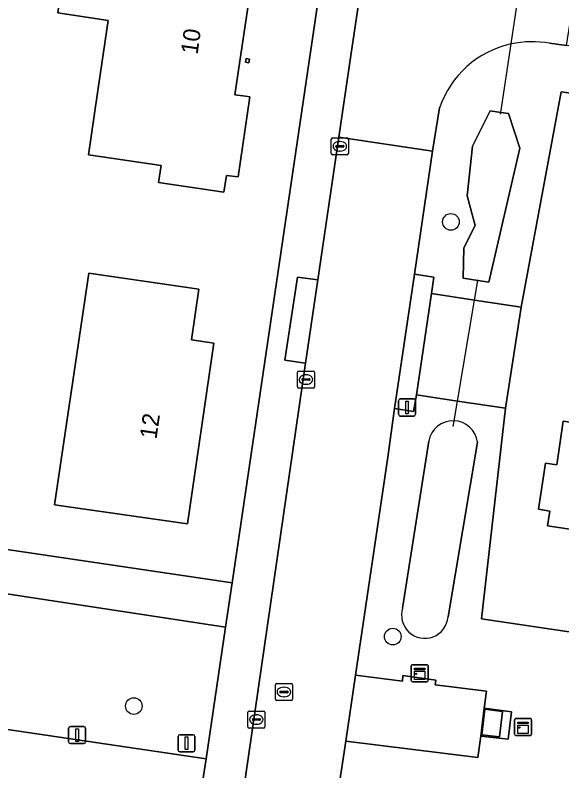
# Model space of a CAD drawing. Extents: x 164148 to 165261, y 382513 to 383432.
# Drawn here: x 164640.66 to 164672.77, y 383009.51 to 383053.88 of the extents above; entities that cross this region are included whole.
import ezdxf

# ---------------------------------------------------------------- set-up
doc = ezdxf.new("R2010")
doc.units = 0
for name, color, linetype in [('IMGEO_Boom', 7, 'Continuous'), ('IMGEO_Duiker', 7, 'Continuous'), ('IMGEO_Erf', 7, 'Continuous'), ('IMGEO_Fietspad_gesloten', 7, 'Continuous'), ('IMGEO_Greppel_droge_sloot', 7, 'Continuous'), ('IMGEO_Groenvoorziening', 7, 'Continuous'), ('IMGEO_Hek', 7, 'Continuous'), ('IMGEO_Kast', 7, 'Continuous'), ('IMGEO_Kolk', 7, 'Continuous'), ('IMGEO_Lichtmast', 7, 'Continuous'), ('IMGEO_Pand', 7, 'Continuous'), ('IMGEO_Pand_nummerreeks', 7, 'Continuous'), ('IMGEO_Rijbaan_lokaal_open', 7, 'Continuous'), ('IMGEO_Rioolput', 7, 'Continuous'), ('IMGEO_Verkeersbordpaal', 7, 'Continuous'), ('IMGEO_Voetpad_gesloten', 7, 'Continuous'), ('IMGEO_Voetpad_open', 7, 'Continuous')]:
    doc.layers.add(name, color=color, linetype=linetype)

msp = doc.modelspace()

# ---------------------------------------------------------------- linework, layer by layer
at = {"layer": 'IMGEO_Boom'}
for centre in [(164666.253, 383041.744), (164662.839, 383017.391), (164647.634, 383013.315)]:
    msp.add_circle(centre, 0.489, dxfattribs=at)
at = {"layer": 'IMGEO_Duiker'}
for points in [[(164669.17, 383048.067), (164669.186, 383048.171), (164669.783, 383052.194), (164670.585, 383057.59), (164670.896, 383059.687), (164671.713, 383065.185), (164671.811, 383065.842)], [(164666.384, 383029.725), (164666.441, 383030.064), (164666.638, 383031.227), (164667.64, 383037.152), (164667.835, 383038.307), (164667.844, 383038.358)]]:
    msp.add_lwpolyline(points, dxfattribs=at)
at = {"layer": 'IMGEO_Erf'}
msp.add_lwpolyline([(164623.816, 383163.728), (164623.27, 383160.3), (164619.179, 383132.443), (164618.352, 383126.809), (164615.891, 383110.249), (164614.945, 383103.98), (164613.433, 383093.793), (164612.816, 383089.325), (164610.85, 383076.068), (164610.275, 383072.012), (164608.947, 383063.175), (164608.549, 383060.35), (164603.815, 383028.066), (164603.697, 383027.909), (164653.403, 383020.558), (164672.613, 383150.649)], dxfattribs=at)
for points in [[(164643.979, 383059.556), (164649.903, 383058.694), (164649.464, 383055.724), (164653.421, 383055.143), (164654.417, 383054.988), (164653.922, 383051.582), (164653.571, 383049.213), (164654.187, 383049.123), (164654.45, 383049.082), (164653.769, 383044.382), (164653.075, 383044.477), (164652.926, 383043.491), (164649.091, 383044.05), (164649.237, 383045.049), (164644.968, 383045.674), (164645.482, 383049.186), (164646.131, 383053.57), (164643.171, 383054.013)], [(164654.422, 383051.297), (164654.384, 383051.092), (164654.191, 383051.127), (164654.228, 383051.332)], [(164773.625, 383034.37), (164756.914, 383036.848), (164756.945, 383037.007), (164750.961, 383037.884), (164745.467, 383038.7), (164743.325, 383039.011), (164732.535, 383040.594), (164726.832, 383041.442), (164721.322, 383042.249), (164719.176, 383042.567), (164708.591, 383044.131), (164702.568, 383045.027), (164697.666, 383045.734), (164696.644, 383045.892), (164694.5, 383046.223), (164676.627, 383048.817), (164672.72, 383049.384), (164670.369, 383036.742), (164669.457, 383030.808), (164668.043, 383018.43), (164792.926, 382999.883), (164794.329, 383009.577), (164793.988, 383009.985)], [(164644.985, 383038.74), (164651.453, 383037.79), (164651.024, 383034.828), (164652.338, 383034.618), (164650.781, 383024.013), (164642.976, 383025.139)], [(164690.562, 383027.137), (164683.784, 383028.147), (164682.464, 383019.289), (164675.536, 383020.322), (164675.979, 383023.295), (164671.929, 383023.898), (164672.059, 383024.768), (164671.396, 383024.867), (164671.8, 383027.577), (164672.463, 383027.479), (164672.845, 383030.044), (164676.882, 383029.443), (164677.368, 383032.706), (164691.087, 383030.663)]]:
    msp.add_lwpolyline(points, close=True, dxfattribs=at)
at = {"layer": 'IMGEO_Fietspad_gesloten'}
msp.add_lwpolyline([(164606.207, 383013.843), (164611.224, 383013.148), (164651.419, 383007.225), (164651.876, 383010.215), (164622.034, 383014.618), (164609.803, 383016.423), (164601.968, 383017.579)], dxfattribs=at)
at = {"layer": 'IMGEO_Greppel_droge_sloot'}
msp.add_lwpolyline([(164669.625, 383048.111), (164669.186, 383048.171), (164668.547, 383048.259), (164667.511, 383046.182), (164667.197, 383043.278), (164667.674, 383041.533), (164667.01, 383040.213), (164666.963, 383038.448), (164667.835, 383038.307), (164668.469, 383038.205), (164670.288, 383046.068)], close=True, dxfattribs=at)
for points in [[(164664.949, 383028.878), (164663.413, 383019.071)], [(164666.087, 383018.551), (164667.82, 383028.802)]]:
    msp.add_lwpolyline(points, dxfattribs=at)
for centre, radius, start, end in [((164666.378, 383028.611), 1.454, 7.5389, 169.4284), ((164664.721, 383018.663), 1.37, 162.681, 355.3096)]:
    msp.add_arc(centre, radius, start, end, dxfattribs=at)
at = {"layer": 'IMGEO_Groenvoorziening'}
for points in [[(164676.401, 383051.606), (164673.036, 383052.095), (164672.044, 383052.229)], [(164672.72, 383049.384), (164676.627, 383048.817), (164676.862, 383050.358), (164676.912, 383050.687)], [(164665.587, 383048.434), (164665.176, 383045.892), (164664.112, 383038.673), (164665.241, 383038.503), (164665.117, 383037.531), (164667.64, 383037.152), (164670.369, 383036.742), (164672.72, 383049.384)], [(164792.926, 382999.883), (164668.043, 383018.43), (164669.457, 383030.808), (164666.638, 383031.227), (164664.234, 383031.584), (164664.063, 383030.618), (164662.945, 383030.79), (164662.544, 383027.92), (164660.646, 383015.127), (164663.404, 383014.779), (164663.437, 383015.117), (164665.365, 383014.843), (164665.318, 383014.554), (164668.337, 383014.189), (164668.204, 383013.184), (164669.801, 383012.974), (164669.613, 383011.378), (164668.005, 383011.557), (164667.823, 383010.303), (164660.073, 383011.264), (164659.708, 383008.804), (164765.127, 382992.769)], [(164663.413, 383019.071), (164664.949, 383028.878)], [(164667.82, 383028.802), (164666.087, 383018.551)]]:
    msp.add_lwpolyline(points, dxfattribs=at)
for points in [[(164670.288, 383046.068), (164668.469, 383038.205), (164667.835, 383038.307), (164666.963, 383038.448), (164667.01, 383040.213), (164667.674, 383041.533), (164667.197, 383043.278), (164667.511, 383046.182), (164668.547, 383048.259), (164669.186, 383048.171), (164669.625, 383048.111)], [(164603.697, 383027.909), (164603.299, 383025.53), (164616.839, 383023.466), (164616.85, 383023.465), (164619.033, 383023.132), (164620.11, 383022.968), (164653.018, 383017.951), (164653.403, 383020.558)], [(164619.033, 383023.132), (164620.384, 383022.746), (164621.194, 383022.137), (164622.173, 383020.201), (164622.505, 383017.94), (164622.45, 383017.085), (164622.034, 383014.618), (164651.876, 383010.215), (164653.018, 383017.951), (164620.11, 383022.968)]]:
    msp.add_lwpolyline(points, close=True, dxfattribs=at)
for centre, radius, start, end in [((164671.001, 383046.587), 5.737, 79.5212, 102.2525), ((164671.002, 383046.613), 5.713, 102.3162, 161.4103), ((164666.378, 383028.611), 1.454, 7.5389, 169.4284), ((164664.721, 383018.663), 1.37, 162.681, 355.3096)]:
    msp.add_arc(centre, radius, start, end, dxfattribs=at)
at = {"layer": 'IMGEO_Hek'}
msp.add_lwpolyline([(164603.697, 383027.909), (164653.403, 383020.558)], dxfattribs=at)
at = {"layer": 'IMGEO_Kast'}
for p, q in [((164663.921, 383014.82), (164663.921, 383015.661)), ((164663.921, 383015.661), (164663.921, 383014.82)), ((164663.996, 383015.745), (164664.837, 383015.745)), ((164664.837, 383015.745), (164663.996, 383015.745)), ((164664.921, 383015.67), (164664.921, 383014.829)), ((164664.921, 383014.829), (164664.921, 383015.67)), ((164664.846, 383014.745), (164664.005, 383014.745)), ((164664.005, 383014.745), (164664.846, 383014.745)), ((164669.991, 383011.662), (164669.991, 383012.503)), ((164669.991, 383012.503), (164669.991, 383011.662)), ((164670.066, 383012.587), (164670.907, 383012.587)), ((164670.907, 383012.587), (164670.066, 383012.587)), ((164670.991, 383012.512), (164670.991, 383011.671)), ((164670.991, 383011.671), (164670.991, 383012.512)), ((164670.916, 383011.587), (164670.075, 383011.587)), ((164670.075, 383011.587), (164670.916, 383011.587))]:
    msp.add_line(p, q, dxfattribs=at)
for points in [[(164664.116, 383015.535), (164664.716, 383015.535), (164664.716, 383015.45), (164664.116, 383015.45), (164664.116, 383015.535)], [(164664.116, 383015.36), (164664.716, 383015.36), (164664.716, 383014.871), (164664.116, 383014.871), (164664.116, 383015.36)], [(164670.186, 383012.377), (164670.786, 383012.377), (164670.786, 383012.292), (164670.186, 383012.292), (164670.186, 383012.377)], [(164670.186, 383012.202), (164670.786, 383012.202), (164670.786, 383011.713), (164670.186, 383011.713), (164670.186, 383012.202)]]:
    msp.add_lwpolyline(points, dxfattribs=at)
for centre in [(164664.2, 383015.209), (164670.27, 383012.051)]:
    msp.add_circle(centre, 0.0377, dxfattribs=at)
for centre, start, end in [((164663.999, 383015.667), 92.4484, 184.2845), ((164663.999, 383015.667), 92.4484, 184.2845), ((164664.843, 383015.667), 2.4484, 94.2845), ((164664.843, 383015.667), 2.4484, 94.2845), ((164663.999, 383014.823), 182.4484, 274.2845), ((164663.999, 383014.823), 182.4484, 274.2845), ((164664.843, 383014.823), 272.4484, 4.2845), ((164664.843, 383014.823), 272.4484, 4.2845), ((164670.069, 383012.509), 92.4484, 184.2845), ((164670.069, 383012.509), 92.4484, 184.2845), ((164670.913, 383012.509), 2.4484, 94.2845), ((164670.913, 383012.509), 2.4484, 94.2845), ((164670.069, 383011.665), 182.4484, 274.2845), ((164670.069, 383011.665), 182.4484, 274.2845), ((164670.913, 383011.665), 272.4484, 4.2845), ((164670.913, 383011.665), 272.4484, 4.2845)]:
    msp.add_arc(centre, 0.0779, start, end, dxfattribs=at)
at = {"layer": 'IMGEO_Kolk'}
for p, q in [((164659.228, 383045.756), (164659.228, 383046.608)), ((164659.303, 383046.682), (164660.155, 383046.682)), ((164659.716, 383046.462), (164659.741, 383046.462)), ((164660.229, 383046.608), (164660.229, 383045.756)), ((164659.487, 383046.176), (164659.487, 383046.188)), ((164659.925, 383046.139), (164659.527, 383046.139)), ((164659.53, 383046.225), (164659.928, 383046.225)), ((164659.971, 383046.188), (164659.971, 383046.176)), ((164660.155, 383045.682), (164659.303, 383045.682)), ((164659.739, 383045.902), (164659.714, 383045.902)), ((164657.238, 383032.062), (164657.238, 383032.914)), ((164657.313, 383032.988), (164658.165, 383032.988)), ((164657.726, 383032.768), (164657.751, 383032.768)), ((164658.239, 383032.914), (164658.239, 383032.062)), ((164657.497, 383032.482), (164657.497, 383032.494)), ((164657.935, 383032.445), (164657.537, 383032.445)), ((164657.54, 383032.531), (164657.938, 383032.531)), ((164657.981, 383032.494), (164657.981, 383032.482)), ((164658.165, 383031.988), (164657.313, 383031.988)), ((164657.749, 383032.208), (164657.724, 383032.208)), ((164654.325, 383012.097), (164654.325, 383012.949)), ((164654.4, 383013.023), (164655.252, 383013.023)), ((164654.813, 383012.803), (164654.838, 383012.803)), ((164655.326, 383012.949), (164655.326, 383012.097)), ((164654.584, 383012.517), (164654.584, 383012.529)), ((164655.022, 383012.48), (164654.624, 383012.48)), ((164654.627, 383012.566), (164655.025, 383012.566)), ((164655.068, 383012.529), (164655.068, 383012.517)), ((164655.252, 383012.023), (164654.4, 383012.023)), ((164654.836, 383012.243), (164654.811, 383012.243))]:
    msp.add_line(p, q, dxfattribs=at)
for points in [[(164659.228, 383045.756), (164659.228, 383046.608)], [(164659.303, 383046.682), (164660.155, 383046.682)], [(164660.229, 383046.608), (164660.229, 383045.756)], [(164660.155, 383045.682), (164659.303, 383045.682)], [(164657.238, 383032.062), (164657.238, 383032.914)], [(164657.313, 383032.988), (164658.165, 383032.988)], [(164658.239, 383032.914), (164658.239, 383032.062)], [(164658.165, 383031.988), (164657.313, 383031.988)], [(164654.325, 383012.097), (164654.325, 383012.949)], [(164654.4, 383013.023), (164655.252, 383013.023)], [(164655.326, 383012.949), (164655.326, 383012.097)], [(164655.252, 383012.023), (164654.4, 383012.023)]]:
    msp.add_lwpolyline(points, dxfattribs=at)
for centre, radius, start, end in [((164659.305, 383046.606), 0.0765, 91.552, 178.448), ((164659.305, 383046.606), 0.0765, 91.552, 178.448), ((164660.153, 383046.606), 0.0765, 1.552, 88.448), ((164660.153, 383046.606), 0.0765, 1.552, 88.448), ((164659.527, 383046.185), 0.0403, 85.8775, 175.7526), ((164659.524, 383046.175), 0.0366, 178.938, 274.7102), ((164659.928, 383046.182), 0.043, 264.8664, 352.4533), ((164659.932, 383046.187), 0.0386, 1.7309, 96.639), ((164659.305, 383045.758), 0.0765, 181.552, 268.448), ((164659.305, 383045.758), 0.0765, 181.552, 268.448), ((164660.153, 383045.758), 0.0765, 271.552, 358.448), ((164660.153, 383045.758), 0.0765, 271.552, 358.448), ((164657.315, 383032.912), 0.0765, 91.552, 178.448), ((164657.315, 383032.912), 0.0765, 91.552, 178.448), ((164658.163, 383032.912), 0.0765, 1.552, 88.448), ((164658.163, 383032.912), 0.0765, 1.552, 88.448), ((164657.537, 383032.491), 0.0403, 85.8775, 175.7526), ((164657.534, 383032.481), 0.0366, 178.938, 274.7102), ((164657.938, 383032.488), 0.043, 264.8664, 352.4533), ((164657.942, 383032.493), 0.0386, 1.7309, 96.639), ((164657.315, 383032.064), 0.0765, 181.552, 268.448), ((164657.315, 383032.064), 0.0765, 181.552, 268.448), ((164658.163, 383032.064), 0.0765, 271.552, 358.448), ((164658.163, 383032.064), 0.0765, 271.552, 358.448), ((164654.402, 383012.947), 0.0765, 91.552, 178.448), ((164654.402, 383012.947), 0.0765, 91.552, 178.448), ((164655.25, 383012.947), 0.0765, 1.552, 88.448), ((164655.25, 383012.947), 0.0765, 1.552, 88.448), ((164654.624, 383012.526), 0.0403, 85.8775, 175.7526), ((164654.621, 383012.516), 0.0366, 178.938, 274.7102), ((164655.025, 383012.523), 0.043, 264.8664, 352.4533), ((164655.029, 383012.528), 0.0386, 1.7309, 96.639), ((164654.402, 383012.099), 0.0765, 181.552, 268.448), ((164654.402, 383012.099), 0.0765, 181.552, 268.448), ((164655.25, 383012.099), 0.0765, 271.552, 358.448), ((164655.25, 383012.099), 0.0765, 271.552, 358.448)]:
    msp.add_arc(centre, radius, start, end, dxfattribs=at)
for centre, major_axis, ratio, start_param, end_param in [((164659.715, 383046.182), (-0.387, 0.002), 0.722429, 4.712389, 7.853982), ((164659.74, 383046.182), (-0.39, 0.002), 0.717154, 1.570796, 4.712389), ((164657.725, 383032.488), (-0.387, 0.002), 0.722429, 4.712389, 7.853982), ((164657.75, 383032.488), (-0.39, 0.002), 0.717154, 1.570796, 4.712389), ((164654.812, 383012.523), (-0.387, 0.002), 0.722429, 4.712389, 7.853982), ((164654.837, 383012.523), (-0.39, 0.002), 0.717154, 1.570796, 4.712389)]:
    msp.add_ellipse(centre, major_axis=major_axis, ratio=ratio, start_param=start_param, end_param=end_param, dxfattribs=at)
at = {"layer": 'IMGEO_Lichtmast'}
for p, q in [((164663.178, 383030.445), (164663.178, 383031.245)), ((164663.178, 383031.245), (164663.178, 383030.445)), ((164663.278, 383031.345), (164664.068, 383031.345)), ((164664.068, 383031.345), (164663.278, 383031.345)), ((164664.168, 383031.245), (164664.168, 383030.445)), ((164664.168, 383030.445), (164664.168, 383031.245)), ((164664.068, 383030.345), (164663.278, 383030.345)), ((164663.278, 383030.345), (164664.068, 383030.345)), ((164643.806, 383011.21), (164643.806, 383012.01)), ((164643.806, 383012.01), (164643.806, 383011.21)), ((164643.906, 383012.11), (164644.696, 383012.11)), ((164644.696, 383012.11), (164643.906, 383012.11)), ((164644.796, 383012.01), (164644.796, 383011.21)), ((164644.796, 383011.21), (164644.796, 383012.01)), ((164644.696, 383011.11), (164643.906, 383011.11)), ((164643.906, 383011.11), (164644.696, 383011.11))]:
    msp.add_line(p, q, dxfattribs=at)
for points in [[(164663.598, 383031.22), (164663.748, 383031.22), (164663.748, 383030.47), (164663.598, 383030.47), (164663.598, 383031.22)], [(164644.226, 383011.985), (164644.376, 383011.985), (164644.376, 383011.235), (164644.226, 383011.235), (164644.226, 383011.985)]]:
    msp.add_lwpolyline(points, dxfattribs=at)
for centre, start, end in [((164663.278, 383031.245), 90, 180), ((164663.278, 383031.245), 90, 180), ((164664.068, 383031.245), 0, 90), ((164664.068, 383031.245), 360, 90), ((164663.278, 383030.445), 180, 270), ((164663.278, 383030.445), 180, 270), ((164664.068, 383030.445), 270, 0), ((164664.068, 383030.445), 270, 0), ((164643.906, 383012.01), 90, 180), ((164643.906, 383012.01), 90, 180), ((164644.696, 383012.01), 0, 90), ((164644.696, 383012.01), 360, 90), ((164643.906, 383011.21), 180, 270), ((164643.906, 383011.21), 180, 270), ((164644.696, 383011.21), 270, 0), ((164644.696, 383011.21), 270, 0)]:
    msp.add_arc(centre, 0.1, start, end, dxfattribs=at)
at = {"layer": 'IMGEO_Pand'}
for points in [[(164654.417, 383054.988), (164653.421, 383055.143), (164649.464, 383055.724), (164649.903, 383058.694), (164643.979, 383059.556), (164643.171, 383054.013), (164646.131, 383053.57), (164645.482, 383049.186), (164644.968, 383045.674), (164649.237, 383045.049), (164649.091, 383044.05), (164652.926, 383043.491), (164653.075, 383044.477), (164653.769, 383044.382), (164654.45, 383049.082), (164654.187, 383049.123), (164653.571, 383049.213), (164653.922, 383051.582)], [(164654.422, 383051.297), (164654.228, 383051.332), (164654.191, 383051.127), (164654.384, 383051.092)], [(164650.781, 383024.013), (164652.338, 383034.618), (164651.024, 383034.828), (164651.453, 383037.79), (164644.985, 383038.74), (164642.976, 383025.139)], [(164683.784, 383028.147), (164690.562, 383027.137), (164691.087, 383030.663), (164677.368, 383032.706), (164676.882, 383029.443), (164672.845, 383030.044), (164672.463, 383027.479), (164671.8, 383027.577), (164671.396, 383024.867), (164672.059, 383024.768), (164671.929, 383023.898), (164675.979, 383023.295), (164675.536, 383020.322), (164682.464, 383019.289)]]:
    msp.add_lwpolyline(points, close=True, dxfattribs=at)
at = {"layer": 'IMGEO_Rijbaan_lokaal_open'}
for points in [[(164668.172, 383066.038), (164668.78, 383070.285), (164663.299, 383071.06), (164660.382, 383051.508), (164659.675, 383046.714), (164665.176, 383045.892), (164665.587, 383048.434)], [(164672.044, 383052.229), (164673.036, 383052.095), (164673.758, 383056.679), (164673.104, 383056.788)]]:
    msp.add_lwpolyline(points, dxfattribs=at)
msp.add_lwpolyline([(164662.544, 383027.92), (164662.945, 383030.79), (164664.112, 383038.673), (164665.176, 383045.892), (164659.675, 383046.714), (164658.441, 383038.338), (164657.714, 383033.452), (164653.078, 383001.462), (164658.504, 383000.69), (164659.275, 383005.882), (164659.708, 383008.804), (164660.073, 383011.264), (164660.646, 383015.127)], close=True, dxfattribs=at)
for centre, radius, start, end in [((164671.001, 383046.587), 5.737, 79.5212, 102.2525), ((164671.002, 383046.613), 5.713, 102.3162, 161.4103)]:
    msp.add_arc(centre, radius, start, end, dxfattribs=at)
at = {"layer": 'IMGEO_Rioolput'}
for p, q in [((164655.944, 383013.718), (164655.944, 383014.57)), ((164656.019, 383014.644), (164656.871, 383014.644)), ((164656.945, 383014.57), (164656.945, 383013.718)), ((164656.203, 383014.138), (164656.203, 383014.15)), ((164656.641, 383014.101), (164656.243, 383014.101)), ((164656.246, 383014.187), (164656.644, 383014.187)), ((164656.432, 383014.424), (164656.457, 383014.424)), ((164656.687, 383014.15), (164656.687, 383014.138)), ((164656.871, 383013.644), (164656.019, 383013.644)), ((164656.455, 383013.864), (164656.43, 383013.864))]:
    msp.add_line(p, q, dxfattribs=at)
for points in [[(164655.944, 383013.718), (164655.944, 383014.57)], [(164656.019, 383014.644), (164656.871, 383014.644)], [(164656.945, 383014.57), (164656.945, 383013.718)], [(164656.871, 383013.644), (164656.019, 383013.644)]]:
    msp.add_lwpolyline(points, dxfattribs=at)
for centre, radius, start, end in [((164656.021, 383014.568), 0.0765, 91.552, 178.448), ((164656.021, 383014.568), 0.0765, 91.552, 178.448), ((164656.869, 383014.568), 0.0765, 1.552, 88.448), ((164656.869, 383014.568), 0.0765, 1.552, 88.448), ((164656.243, 383014.147), 0.0403, 85.8775, 175.7526), ((164656.24, 383014.137), 0.0366, 178.938, 274.7102), ((164656.644, 383014.144), 0.043, 264.8664, 352.4533), ((164656.648, 383014.149), 0.0386, 1.7309, 96.639), ((164656.021, 383013.72), 0.0765, 181.552, 268.448), ((164656.021, 383013.72), 0.0765, 181.552, 268.448), ((164656.869, 383013.72), 0.0765, 271.552, 358.448), ((164656.869, 383013.72), 0.0765, 271.552, 358.448)]:
    msp.add_arc(centre, radius, start, end, dxfattribs=at)
for centre, major_axis, ratio, start_param, end_param in [((164656.431, 383014.144), (-0.387, 0.002), 0.722429, 4.712389, 7.853982), ((164656.456, 383014.144), (-0.39, 0.002), 0.717154, 1.570796, 4.712389)]:
    msp.add_ellipse(centre, major_axis=major_axis, ratio=ratio, start_param=start_param, end_param=end_param, dxfattribs=at)
at = {"layer": 'IMGEO_Verkeersbordpaal'}
for p, q in [((164650.23, 383010.733), (164650.23, 383011.533)), ((164650.23, 383011.533), (164650.23, 383010.733)), ((164650.33, 383011.633), (164651.12, 383011.633)), ((164651.12, 383011.633), (164650.33, 383011.633)), ((164651.22, 383011.533), (164651.22, 383010.733)), ((164651.22, 383010.733), (164651.22, 383011.533)), ((164651.12, 383010.633), (164650.33, 383010.633)), ((164650.33, 383010.633), (164651.12, 383010.633))]:
    msp.add_line(p, q, dxfattribs=at)
msp.add_lwpolyline([(164650.65, 383011.508), (164650.8, 383011.508), (164650.8, 383010.758), (164650.65, 383010.758), (164650.65, 383011.508)], dxfattribs=at)
for centre, start, end in [((164650.33, 383011.533), 90, 180), ((164650.33, 383011.533), 90, 180), ((164651.12, 383011.533), 0, 90), ((164651.12, 383011.533), 360, 90), ((164650.33, 383010.733), 180, 270), ((164650.33, 383010.733), 180, 270), ((164651.12, 383010.733), 270, 0), ((164651.12, 383010.733), 270, 0)]:
    msp.add_arc(centre, 0.1, start, end, dxfattribs=at)
at = {"layer": 'IMGEO_Voetpad_gesloten'}
for points in [[(164668.204, 383013.184), (164668.005, 383011.557), (164669.613, 383011.378), (164669.801, 383012.974)], [(164669.281, 383013.003), (164669.106, 383011.507), (164668.069, 383011.621), (164668.235, 383013.124)], [(164669.281, 383013.003), (164668.235, 383013.124), (164668.069, 383011.621), (164669.106, 383011.507)]]:
    msp.add_lwpolyline(points, close=True, dxfattribs=at)
at = {"layer": 'IMGEO_Voetpad_open'}
msp.add_lwpolyline([(164672.613, 383150.649), (164653.403, 383020.558), (164653.018, 383017.951), (164651.876, 383010.215), (164651.419, 383007.225), (164650.705, 383001.947), (164653.078, 383001.462), (164657.714, 383033.452), (164656.509, 383033.621), (164657.237, 383038.501), (164658.441, 383038.338), (164659.675, 383046.714), (164660.382, 383051.508), (164663.299, 383071.06), (164663.405, 383071.768), (164663.423, 383071.905), (164662.198, 383072.123), (164662.932, 383077.035), (164664.173, 383076.85), (164666.161, 383090.76)], dxfattribs=at)
for points in [[(164658.441, 383038.338), (164657.237, 383038.501), (164656.509, 383033.621), (164657.714, 383033.452)], [(164665.117, 383037.531), (164665.241, 383038.503), (164664.112, 383038.673), (164662.945, 383030.79), (164664.063, 383030.618), (164664.234, 383031.584)], [(164670.369, 383036.742), (164667.64, 383037.152), (164665.117, 383037.531), (164664.234, 383031.584), (164666.638, 383031.227), (164669.457, 383030.808)], [(164668.204, 383013.184), (164668.337, 383014.189), (164665.318, 383014.554), (164665.365, 383014.843), (164663.437, 383015.117), (164663.404, 383014.779), (164660.646, 383015.127), (164660.073, 383011.264), (164667.823, 383010.303), (164668.005, 383011.557)]]:
    msp.add_lwpolyline(points, close=True, dxfattribs=at)

# ---------------------------------------------------------------- texts
at = {"layer": 'IMGEO_Pand_nummerreeks'}
for s, rotation, p in [('10', 82.1983, (164651.375, 383051.541)), ('12', 81.6468, (164648.959, 383028.951))]:
    msp.add_text(s, height=1, rotation=rotation, dxfattribs=at).set_placement(p)

doc.saveas('drawing.dxf')
